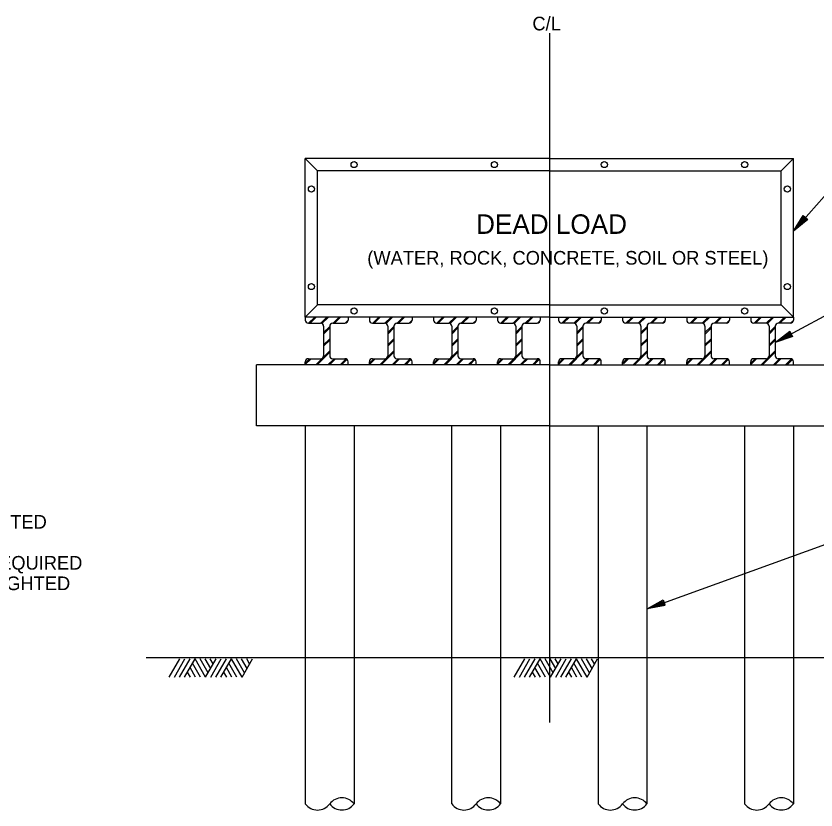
# Model space of a CAD drawing. Extents: x 22378.6 to 22422.6, y 22377.7 to 22411.7.
# Drawn here: x 22398.72 to 22406.91, y 22384.19 to 22392.32 of the extents above; entities that cross this region are included whole.
import ezdxf

# ---------------------------------------------------------------- set-up
doc = ezdxf.new("R2010")
doc.units = 0
for name, color, linetype in [('Level 1', 7, 'Continuous'), ('Level 10', 7, 'Continuous'), ('Level 2', 7, 'Continuous'), ('Level 4', 7, 'Continuous'), ('Level 7', 7, 'Continuous')]:
    doc.layers.add(name, color=color, linetype=linetype)

msp = doc.modelspace()

# ---------------------------------------------------------------- linework, layer by layer
at = {"layer": 'Level 1'}
for p, q in [((22404.1812, 22392.1476), (22404.1812, 22385.0825)), ((22406.7157, 22390.1563), (22406.7157, 22390.1563)), ((22406.6812, 22390.1173), (22406.6812, 22390.1173)), ((22401.6812, 22389.2377), (22401.6812, 22389.2064)), ((22401.7155, 22389.1753), (22401.7778, 22389.2377)), ((22401.7302, 22389.1753), (22401.7926, 22389.2377)), ((22401.8402, 22389.1751), (22401.9028, 22389.2377)), ((22401.8512, 22389.1713), (22401.9176, 22389.2377)), ((22401.9654, 22389.1752), (22402.0279, 22389.2377)), ((22401.9801, 22389.1752), (22402.0426, 22389.2377)), ((22402.1187, 22389.2377), (22402.1187, 22389.2064)), ((22402.3375, 22389.2377), (22402.3375, 22389.2064)), ((22402.3717, 22389.1752), (22402.4341, 22389.2377)), ((22402.3864, 22389.1752), (22402.4488, 22389.2377)), ((22402.4959, 22389.1744), (22402.5591, 22389.2377)), ((22402.5082, 22389.1721), (22402.5738, 22389.2377)), ((22402.6216, 22389.1751), (22402.6841, 22389.2377)), ((22402.6363, 22389.1751), (22402.6988, 22389.2377)), ((22402.775, 22389.2377), (22402.775, 22389.2064)), ((22402.9937, 22389.2377), (22402.9937, 22389.2064)), ((22403.0278, 22389.1751), (22403.0904, 22389.2377)), ((22403.0425, 22389.1751), (22403.1051, 22389.2377)), ((22403.1515, 22389.1738), (22403.2154, 22389.2377)), ((22403.1633, 22389.1709), (22403.2301, 22389.2377)), ((22403.2778, 22389.1751), (22403.3404, 22389.2377)), ((22403.2925, 22389.1751), (22403.3551, 22389.2377)), ((22403.4312, 22389.2377), (22403.4312, 22389.2064)), ((22403.65, 22389.2377), (22403.65, 22389.2064)), ((22403.684, 22389.1751), (22403.7466, 22389.2377)), ((22403.6987, 22389.1751), (22403.7613, 22389.2377)), ((22403.8093, 22389.1754), (22403.8716, 22389.2377)), ((22403.8203, 22389.1716), (22403.8863, 22389.2377)), ((22403.9342, 22389.1752), (22403.9966, 22389.2377)), ((22403.9489, 22389.1752), (22404.0113, 22389.2377)), ((22404.0875, 22389.2377), (22404.0875, 22389.2064)), ((22404.275, 22389.2377), (22404.275, 22389.2064)), ((22404.3091, 22389.1751), (22404.3717, 22389.2377)), ((22404.3238, 22389.1751), (22404.3864, 22389.2377)), ((22404.4327, 22389.1737), (22404.4967, 22389.2377)), ((22404.4448, 22389.1712), (22404.5113, 22389.2377)), ((22404.559, 22389.1751), (22404.6217, 22389.2377)), ((22404.5737, 22389.1751), (22404.6363, 22389.2377)), ((22404.7125, 22389.2377), (22404.7125, 22389.2064)), ((22404.9312, 22389.2377), (22404.9312, 22389.2064)), ((22404.9653, 22389.1751), (22405.0278, 22389.2377)), ((22404.98, 22389.1751), (22405.0425, 22389.2377)), ((22405.0905, 22389.1754), (22405.1528, 22389.2377)), ((22405.1018, 22389.1719), (22405.1675, 22389.2377)), ((22405.2154, 22389.1752), (22405.2778, 22389.2377)), ((22405.2301, 22389.1752), (22405.2925, 22389.2377)), ((22405.3687, 22389.2377), (22405.3687, 22389.2064)), ((22405.5875, 22389.2377), (22405.5875, 22389.2064)), ((22405.6217, 22389.1752), (22405.6841, 22389.2377)), ((22405.6364, 22389.1752), (22405.6988, 22389.2377)), ((22405.7462, 22389.1747), (22405.8091, 22389.2377)), ((22405.757, 22389.1708), (22405.8238, 22389.2377)), ((22405.8716, 22389.1752), (22405.9341, 22389.2377)), ((22405.8863, 22389.1752), (22405.9488, 22389.2377)), ((22406.025, 22389.2377), (22406.025, 22389.2064)), ((22406.2437, 22389.2377), (22406.2437, 22389.2064)), ((22406.2779, 22389.1752), (22406.3404, 22389.2377)), ((22406.2926, 22389.1752), (22406.3551, 22389.2377)), ((22406.4018, 22389.1741), (22406.4654, 22389.2377)), ((22406.4139, 22389.1716), (22406.4801, 22389.2377)), ((22406.5278, 22389.1751), (22406.5904, 22389.2377)), ((22406.5425, 22389.1751), (22406.6051, 22389.2377)), ((22406.6812, 22389.2377), (22406.6812, 22389.2064)), ((22401.7125, 22389.1752), (22401.8375, 22389.1752)), ((22401.8687, 22389.1439), (22401.8687, 22388.8419)), ((22401.8687, 22389.0786), (22401.9312, 22389.1411)), ((22401.9312, 22389.1439), (22401.9312, 22388.8419)), ((22401.9625, 22389.1752), (22402.0875, 22389.1752)), ((22402.0905, 22389.1753), (22402.1184, 22389.2032)), ((22402.3687, 22389.1752), (22402.4937, 22389.1752)), ((22402.525, 22389.1439), (22402.525, 22388.8419)), ((22402.525, 22389.0786), (22402.5874, 22389.1411)), ((22402.5875, 22389.1439), (22402.5875, 22388.8419)), ((22402.6187, 22389.1752), (22402.7437, 22389.1752)), ((22402.7459, 22389.1744), (22402.7734, 22389.2021)), ((22403.025, 22389.1752), (22403.15, 22389.1752)), ((22403.1812, 22389.1439), (22403.1812, 22388.8419)), ((22403.1812, 22389.0786), (22403.2437, 22389.1411)), ((22403.2437, 22389.1439), (22403.2437, 22388.8419)), ((22403.275, 22389.1752), (22403.4, 22389.1752)), ((22403.4045, 22389.1768), (22403.4316, 22389.2039)), ((22403.6812, 22389.1752), (22403.8062, 22389.1752)), ((22403.8375, 22389.1439), (22403.8375, 22388.8419)), ((22403.8375, 22389.0786), (22403.9, 22389.1411)), ((22403.9, 22389.1439), (22403.9, 22388.8419)), ((22403.9312, 22389.1752), (22404.0562, 22389.1752)), ((22404.0598, 22389.1759), (22404.0865, 22389.2026)), ((22404.4312, 22389.1752), (22404.3062, 22389.1752)), ((22404.4625, 22389.1439), (22404.4625, 22388.8419)), ((22404.4625, 22389.0786), (22404.525, 22389.1411)), ((22404.525, 22389.1439), (22404.525, 22388.8419)), ((22404.6812, 22389.1752), (22404.5562, 22389.1752)), ((22404.6857, 22389.1767), (22404.7132, 22389.2043)), ((22405.0875, 22389.1752), (22404.9625, 22389.1752)), ((22405.1187, 22389.1439), (22405.1187, 22388.8419)), ((22405.1187, 22389.0786), (22405.1812, 22389.1411)), ((22405.1812, 22389.1439), (22405.1812, 22388.8419)), ((22405.3375, 22389.1752), (22405.2125, 22389.1752)), ((22405.341, 22389.1758), (22405.3682, 22389.2031)), ((22405.7437, 22389.1752), (22405.6187, 22389.1752)), ((22405.7749, 22389.0786), (22405.8374, 22389.1411)), ((22405.775, 22389.1439), (22405.775, 22388.8419)), ((22405.8375, 22389.1439), (22405.8375, 22388.8419)), ((22405.9937, 22389.1752), (22405.8687, 22389.1752)), ((22405.9963, 22389.1749), (22406.0232, 22389.2017)), ((22406.4, 22389.1752), (22406.275, 22389.1752)), ((22406.4312, 22389.1439), (22406.4312, 22388.8419)), ((22406.4312, 22389.0786), (22406.4937, 22389.1411)), ((22406.4937, 22389.1439), (22406.4937, 22388.8419)), ((22406.65, 22389.1752), (22406.525, 22389.1752)), ((22406.6549, 22389.1773), (22406.6813, 22389.2036)), ((22401.8687, 22389.0638), (22401.9312, 22389.1263)), ((22402.525, 22389.0639), (22402.5874, 22389.1263)), ((22403.1812, 22389.0638), (22403.2437, 22389.1264)), ((22403.8375, 22389.0638), (22403.9, 22389.1263)), ((22404.4625, 22389.0638), (22404.525, 22389.1264)), ((22405.1187, 22389.0638), (22405.1812, 22389.1263)), ((22405.7739, 22389.059), (22405.8364, 22389.1215)), ((22406.4312, 22389.0639), (22406.4937, 22389.1263)), ((22401.8687, 22388.9536), (22401.9312, 22389.0161)), ((22401.8687, 22388.9388), (22401.9312, 22389.0013)), ((22402.525, 22388.9536), (22402.5874, 22389.0161)), ((22402.525, 22388.9388), (22402.5874, 22389.0013)), ((22403.1812, 22388.9536), (22403.2437, 22389.0161)), ((22403.1812, 22388.9388), (22403.2437, 22389.0013)), ((22403.8375, 22388.9536), (22403.9, 22389.0161)), ((22403.8375, 22388.9388), (22403.9, 22389.0013)), ((22404.4625, 22388.9536), (22404.525, 22389.0161)), ((22404.4625, 22388.9388), (22404.525, 22389.0013)), ((22405.1187, 22388.9536), (22405.1812, 22389.0161)), ((22405.1187, 22388.9388), (22405.1812, 22389.0013)), ((22405.7749, 22388.9536), (22405.8374, 22389.0161)), ((22405.7749, 22388.9388), (22405.8374, 22389.0013)), ((22406.4312, 22388.9536), (22406.4937, 22389.0161)), ((22406.4312, 22388.9388), (22406.4937, 22389.0013)), ((22406.4937, 22388.9771), (22406.4937, 22388.9771)), ((22406.5395, 22389.0018), (22406.5395, 22389.0018)), ((22401.6812, 22388.7661), (22401.7259, 22388.8107)), ((22401.6812, 22388.7513), (22401.7406, 22388.8107)), ((22401.7125, 22388.8107), (22401.8375, 22388.8107)), ((22401.7884, 22388.7482), (22401.9312, 22388.8911)), ((22401.8031, 22388.7482), (22401.9312, 22388.8763)), ((22401.9134, 22388.7482), (22401.9759, 22388.8107)), ((22401.9281, 22388.7482), (22401.9906, 22388.8107)), ((22401.9625, 22388.8107), (22402.0875, 22388.8107)), ((22402.3375, 22388.7661), (22402.3821, 22388.8106)), ((22402.3375, 22388.7513), (22402.3968, 22388.8106)), ((22402.3687, 22388.8107), (22402.4937, 22388.8107)), ((22402.4447, 22388.7482), (22402.5874, 22388.8911)), ((22402.4593, 22388.7482), (22402.5874, 22388.8763)), ((22402.5696, 22388.7482), (22402.6321, 22388.8107)), ((22402.5843, 22388.7482), (22402.6468, 22388.8107)), ((22402.6187, 22388.8107), (22402.7437, 22388.8107)), ((22402.9937, 22388.7661), (22403.0382, 22388.8106)), ((22402.9937, 22388.7513), (22403.053, 22388.8106)), ((22403.025, 22388.8107), (22403.15, 22388.8107)), ((22403.1009, 22388.7481), (22403.2437, 22388.8911)), ((22403.1155, 22388.7481), (22403.2437, 22388.8763)), ((22403.2259, 22388.7481), (22403.2883, 22388.8106)), ((22403.2405, 22388.7481), (22403.303, 22388.8106)), ((22403.275, 22388.8107), (22403.4, 22388.8107)), ((22403.65, 22388.7661), (22403.6947, 22388.8107)), ((22403.65, 22388.7513), (22403.7094, 22388.8107)), ((22403.6812, 22388.8107), (22403.8062, 22388.8107)), ((22403.7571, 22388.7482), (22403.9, 22388.8911)), ((22403.7718, 22388.7482), (22403.9, 22388.8763)), ((22403.8821, 22388.7482), (22403.9447, 22388.8108)), ((22403.8968, 22388.7482), (22403.9594, 22388.8108)), ((22403.9312, 22388.8107), (22404.0562, 22388.8107)), ((22404.275, 22388.7661), (22404.3195, 22388.8106)), ((22404.275, 22388.7513), (22404.3342, 22388.8106)), ((22404.4312, 22388.8107), (22404.3062, 22388.8107)), ((22404.3821, 22388.7481), (22404.525, 22388.8911)), ((22404.3968, 22388.7481), (22404.525, 22388.8763)), ((22404.5071, 22388.7481), (22404.5696, 22388.8106)), ((22404.5218, 22388.7481), (22404.5843, 22388.8106)), ((22404.6812, 22388.8107), (22404.5562, 22388.8107)), ((22404.9339, 22388.7687), (22404.9759, 22388.8107)), ((22404.9397, 22388.7597), (22404.9906, 22388.8107)), ((22405.0875, 22388.8107), (22404.9625, 22388.8107)), ((22405.0384, 22388.7482), (22405.1812, 22388.8911)), ((22405.0531, 22388.7482), (22405.1812, 22388.8763)), ((22405.1634, 22388.7482), (22405.2258, 22388.8106)), ((22405.178, 22388.7482), (22405.2404, 22388.8106)), ((22405.3375, 22388.8107), (22405.2125, 22388.8107)), ((22405.5875, 22388.7661), (22405.6321, 22388.8107)), ((22405.5875, 22388.7513), (22405.6468, 22388.8107)), ((22405.7437, 22388.8107), (22405.6187, 22388.8107)), ((22405.6946, 22388.7482), (22405.8374, 22388.8911)), ((22405.7093, 22388.7482), (22405.8374, 22388.8763)), ((22405.8196, 22388.7482), (22405.8822, 22388.8107)), ((22405.8343, 22388.7482), (22405.8969, 22388.8107)), ((22405.9937, 22388.8107), (22405.8687, 22388.8107)), ((22406.2437, 22388.7661), (22406.2883, 22388.8106)), ((22406.2437, 22388.7513), (22406.303, 22388.8106)), ((22406.4, 22388.8107), (22406.275, 22388.8107)), ((22406.3509, 22388.7482), (22406.4937, 22388.8911)), ((22406.3656, 22388.7482), (22406.4937, 22388.8762)), ((22406.4759, 22388.7482), (22406.5383, 22388.8107)), ((22406.4906, 22388.7482), (22406.5531, 22388.8107)), ((22406.65, 22388.8107), (22406.525, 22388.8107)), ((22401.6812, 22388.7482), (22401.6812, 22388.7794)), ((22402.0384, 22388.7482), (22402.0992, 22388.8091)), ((22402.0531, 22388.7482), (22402.1072, 22388.8023)), ((22402.1187, 22388.7482), (22402.1187, 22388.7794)), ((22402.3375, 22388.7482), (22402.3375, 22388.7794)), ((22402.6947, 22388.7482), (22402.7548, 22388.8083)), ((22402.7094, 22388.7482), (22402.7632, 22388.8021)), ((22402.775, 22388.7482), (22402.775, 22388.7794)), ((22402.9937, 22388.7482), (22402.9937, 22388.7794)), ((22403.3509, 22388.7481), (22403.4103, 22388.8076)), ((22403.3656, 22388.7481), (22403.4193, 22388.8019)), ((22403.4312, 22388.7482), (22403.4312, 22388.7794)), ((22403.65, 22388.7482), (22403.65, 22388.7794)), ((22404.0071, 22388.7482), (22404.0679, 22388.8089)), ((22404.0218, 22388.7482), (22404.0771, 22388.8036)), ((22404.0875, 22388.7482), (22404.0875, 22388.7794)), ((22404.275, 22388.7482), (22404.275, 22388.7794)), ((22404.6321, 22388.7481), (22404.6927, 22388.8087)), ((22404.6468, 22388.7481), (22404.701, 22388.8023)), ((22404.7125, 22388.7482), (22404.7125, 22388.7794)), ((22404.9312, 22388.7482), (22404.9312, 22388.7794)), ((22405.2884, 22388.7482), (22405.3482, 22388.8081)), ((22405.303, 22388.7482), (22405.357, 22388.8021)), ((22405.3687, 22388.7482), (22405.3687, 22388.7794)), ((22405.5875, 22388.7482), (22405.5875, 22388.7794)), ((22405.9446, 22388.7482), (22406.0058, 22388.8093)), ((22405.9593, 22388.7482), (22406.0131, 22388.8019)), ((22406.025, 22388.7482), (22406.025, 22388.7794)), ((22406.2437, 22388.7482), (22406.2437, 22388.7794)), ((22406.6009, 22388.7482), (22406.6613, 22388.8086)), ((22406.6156, 22388.7482), (22406.6709, 22388.8036)), ((22406.6812, 22388.7482), (22406.6812, 22388.7794)), ((22405.1812, 22386.2472), (22405.1812, 22386.2472)), ((22405.2301, 22386.2649), (22405.2301, 22386.2649)), ((22400.2882, 22385.5474), (22400.3964, 22385.7349)), ((22400.3402, 22385.5474), (22400.4484, 22385.7349)), ((22400.3922, 22385.5474), (22400.5004, 22385.7349)), ((22400.4441, 22385.5474), (22400.5523, 22385.7349)), ((22400.6606, 22385.5474), (22400.5523, 22385.7349)), ((22400.6866, 22385.5924), (22400.6043, 22385.7349)), ((22400.7126, 22385.6374), (22400.6563, 22385.7349)), ((22400.6606, 22385.5474), (22400.7688, 22385.7348)), ((22400.7386, 22385.6824), (22400.7083, 22385.7349)), ((22400.7126, 22385.5474), (22400.8209, 22385.7349)), ((22400.7644, 22385.5474), (22400.8728, 22385.7349)), ((22400.8164, 22385.5474), (22400.9248, 22385.7349)), ((22401.0331, 22385.5474), (22400.9248, 22385.7349)), ((22401.0591, 22385.5924), (22400.9768, 22385.7349)), ((22401.0851, 22385.6374), (22401.0288, 22385.7349)), ((22401.0331, 22385.5474), (22401.1414, 22385.7349)), ((22401.1111, 22385.6824), (22401.0808, 22385.7349)), ((22403.8216, 22385.5474), (22403.9299, 22385.7349)), ((22403.8736, 22385.5474), (22403.9819, 22385.7349)), ((22403.9256, 22385.5474), (22404.0339, 22385.7349)), ((22403.9775, 22385.5474), (22404.0857, 22385.7349)), ((22404.194, 22385.5474), (22404.0857, 22385.7349)), ((22404.22, 22385.5924), (22404.1377, 22385.7349)), ((22404.246, 22385.6374), (22404.1897, 22385.7349)), ((22404.194, 22385.5474), (22404.3022, 22385.7348)), ((22404.272, 22385.6824), (22404.2417, 22385.7349)), ((22404.246, 22385.5474), (22404.3544, 22385.7349)), ((22404.2979, 22385.5474), (22404.4062, 22385.7349)), ((22404.3499, 22385.5474), (22404.4582, 22385.7349)), ((22404.5665, 22385.5474), (22404.4582, 22385.7349)), ((22404.5925, 22385.5924), (22404.5102, 22385.7349)), ((22404.6185, 22385.6374), (22404.5622, 22385.7349)), ((22404.5665, 22385.5474), (22404.6749, 22385.7349)), ((22404.6445, 22385.6824), (22404.6142, 22385.7349)), ((22400.5566, 22385.5474), (22400.5003, 22385.6449)), ((22400.6086, 22385.5474), (22400.5263, 22385.6899)), ((22400.9291, 22385.5474), (22400.8728, 22385.6449)), ((22400.9811, 22385.5474), (22400.8988, 22385.6899)), ((22404.09, 22385.5474), (22404.0337, 22385.6449)), ((22404.142, 22385.5474), (22404.0597, 22385.6899)), ((22404.4625, 22385.5474), (22404.4062, 22385.6449)), ((22404.5145, 22385.5474), (22404.4322, 22385.6899)), ((22400.5047, 22385.5474), (22400.4744, 22385.5999)), ((22400.8772, 22385.5474), (22400.8469, 22385.5999)), ((22404.0381, 22385.5474), (22404.0079, 22385.5999)), ((22404.4106, 22385.5474), (22404.3804, 22385.5999))]:
    msp.add_line(p, q, dxfattribs=at)
for points in [[(22406.6812, 22390.1173), (22407.3105, 22390.8281), (22407.6069, 22390.8281)], [(22406.8284, 22390.2368), (22406.6812, 22390.1173), (22406.782, 22390.2779), (22406.8217, 22390.2428), (22406.7157, 22390.1563), (22406.7842, 22390.2653), (22406.8096, 22390.2427), (22406.7489, 22390.1937), (22406.7864, 22390.2527), (22406.7968, 22390.2434), (22406.7833, 22390.2326)], [(22406.4937, 22388.9771), (22407.2684, 22389.3939), (22407.5648, 22389.3939)], [(22406.6731, 22389.0384), (22406.4937, 22388.9771), (22406.6437, 22389.093), (22406.6688, 22389.0464), (22406.5395, 22389.0018), (22406.6414, 22389.0804), (22406.6575, 22389.0505), (22406.5836, 22389.0255), (22406.6391, 22389.0679), (22406.6457, 22389.0555), (22406.6294, 22389.0501)], [(22405.1812, 22386.2472), (22407.7285, 22387.1692), (22408.0249, 22387.1692)], [(22405.3676, 22386.2817), (22405.1812, 22386.2472), (22405.3465, 22386.34), (22405.3646, 22386.2902), (22405.2301, 22386.2649), (22405.3424, 22386.3279), (22405.354, 22386.2959), (22405.2771, 22386.2819), (22405.3383, 22386.3158), (22405.3431, 22386.3026), (22405.326, 22386.2996)]]:
    msp.add_lwpolyline(points, dxfattribs=at)
for centre in [(22402.1812, 22390.8002), (22403.6187, 22390.8002), (22404.7437, 22390.8002), (22406.1812, 22390.8002), (22401.7437, 22390.5502), (22406.6187, 22390.5502), (22401.7437, 22389.5502), (22406.6187, 22389.5502), (22402.1812, 22389.3002), (22403.6187, 22389.3002), (22404.7437, 22389.3002), (22406.1812, 22389.3002)]:
    msp.add_circle(centre, 0.0313, dxfattribs=at)
for centre, radius, start, end in [((22401.7124, 22389.2064), 0.0311, 179.85557, 270.33541), ((22401.8374, 22389.1439), 0.0314, 0.12099, 89.68802), ((22401.9625, 22389.144), 0.0313, 89.99062, 180.00938), ((22402.0875, 22389.2064), 0.0312, 269.98594, 0.01406), ((22402.3687, 22389.2064), 0.0312, 179.98594, 270.01406), ((22402.4937, 22389.144), 0.0313, 359.99062, 90.00938), ((22402.6187, 22389.1441), 0.0311, 89.85557, 180.33541), ((22402.7437, 22389.2066), 0.0314, 270.12099, 359.68802), ((22403.0249, 22389.2064), 0.0311, 179.85557, 270.33541), ((22403.1499, 22389.1439), 0.0314, 0.12099, 89.68802), ((22403.275, 22389.144), 0.0313, 89.99062, 180.00938), ((22403.4, 22389.2064), 0.0312, 269.98594, 0.01406), ((22403.6812, 22389.2064), 0.0312, 179.98594, 270.01406), ((22403.8062, 22389.144), 0.0313, 359.99062, 90.00938), ((22403.9312, 22389.1441), 0.0311, 89.85557, 180.33541), ((22404.0562, 22389.2066), 0.0314, 270.12099, 359.68802), ((22404.3062, 22389.2064), 0.0312, 179.98594, 270.01405), ((22404.4312, 22389.144), 0.0313, 359.99061, 90.00938), ((22404.5564, 22389.1439), 0.0314, 90.31198, 179.87901), ((22404.6814, 22389.2064), 0.0311, 269.66458, 0.14443), ((22404.9626, 22389.2066), 0.0314, 180.31197, 269.879), ((22405.0876, 22389.1441), 0.0311, 359.66458, 90.14443), ((22405.2125, 22389.144), 0.0313, 89.99061, 180.00938), ((22405.3375, 22389.2064), 0.0312, 269.98594, 0.01405), ((22405.6187, 22389.2064), 0.0312, 179.98594, 270.01405), ((22405.7437, 22389.144), 0.0313, 359.99061, 90.00938), ((22405.8689, 22389.1439), 0.0314, 90.31198, 179.87901), ((22405.9939, 22389.2064), 0.0311, 269.66458, 0.14443), ((22406.2751, 22389.2066), 0.0314, 180.31197, 269.879), ((22406.4001, 22389.1441), 0.0311, 359.66458, 90.14443), ((22406.525, 22389.144), 0.0313, 89.99061, 180.00938), ((22406.65, 22389.2064), 0.0312, 269.98594, 0.01405), ((22401.7125, 22388.7795), 0.0313, 89.99062, 180.00938), ((22401.8375, 22388.8419), 0.0312, 269.98594, 0.01406), ((22401.9624, 22388.8419), 0.0311, 179.85557, 270.33541), ((22402.0874, 22388.7794), 0.0314, 0.12099, 89.68802), ((22402.3687, 22388.7796), 0.0311, 89.85557, 180.33541), ((22402.4937, 22388.8421), 0.0314, 270.12099, 359.68802), ((22402.6187, 22388.8419), 0.0312, 179.98594, 270.01406), ((22402.7437, 22388.7795), 0.0313, 359.99062, 90.00938), ((22403.025, 22388.7795), 0.0313, 89.99062, 180.00938), ((22403.15, 22388.8419), 0.0312, 269.98594, 0.01406), ((22403.2749, 22388.8419), 0.0311, 179.85557, 270.33541), ((22403.3999, 22388.7794), 0.0314, 0.12099, 89.68802), ((22403.6812, 22388.7796), 0.0311, 89.85557, 180.33541), ((22403.8062, 22388.8421), 0.0314, 270.12099, 359.68802), ((22403.9312, 22388.8419), 0.0312, 179.98594, 270.01406), ((22404.0562, 22388.7795), 0.0313, 359.99062, 90.00938), ((22404.3064, 22388.7794), 0.0314, 90.31198, 179.87901), ((22404.4314, 22388.8419), 0.0311, 269.66458, 0.14443), ((22404.5562, 22388.8419), 0.0312, 179.98594, 270.01405), ((22404.6812, 22388.7795), 0.0313, 359.99061, 90.00938), ((22404.9625, 22388.7795), 0.0313, 89.99061, 180.00938), ((22405.0875, 22388.8419), 0.0312, 269.98594, 0.01405), ((22405.2126, 22388.8421), 0.0314, 180.31197, 269.879), ((22405.3376, 22388.7796), 0.0311, 359.66458, 90.14443), ((22405.6189, 22388.7794), 0.0314, 90.31198, 179.87901), ((22405.7439, 22388.8419), 0.0311, 269.66458, 0.14443), ((22405.8687, 22388.8419), 0.0312, 179.98594, 270.01405), ((22405.9937, 22388.7795), 0.0313, 359.99061, 90.00938), ((22406.275, 22388.7795), 0.0313, 89.99061, 180.00938), ((22406.4, 22388.8419), 0.0312, 269.98594, 0.01405), ((22406.5251, 22388.8421), 0.0314, 180.31198, 269.87901), ((22406.6501, 22388.7796), 0.0311, 359.66458, 90.14443)]:
    msp.add_arc(centre, radius, start, end, dxfattribs=at)
at = {"layer": 'Level 2'}
for p, q in [((22404.1812, 22390.8627), (22401.6812, 22390.8627)), ((22401.6812, 22389.2377), (22401.6812, 22390.8627)), ((22401.6812, 22390.8627), (22401.8062, 22390.7377)), ((22404.1812, 22390.8627), (22406.6812, 22390.8627)), ((22406.6812, 22390.8627), (22406.5562, 22390.7377)), ((22406.6812, 22389.2377), (22406.6812, 22390.8627)), ((22401.8062, 22389.3627), (22401.8062, 22390.7377)), ((22404.1812, 22390.7377), (22401.8062, 22390.7377)), ((22404.1812, 22390.7377), (22406.5562, 22390.7377)), ((22406.5562, 22389.3627), (22406.5562, 22390.7377)), ((22401.6812, 22389.2377), (22401.8062, 22389.3627)), ((22404.1812, 22389.3627), (22401.8062, 22389.3627)), ((22404.1812, 22389.3627), (22406.5562, 22389.3627)), ((22406.6812, 22389.2377), (22406.5562, 22389.3627)), ((22404.1812, 22389.2377), (22401.6812, 22389.2377)), ((22404.1812, 22389.2377), (22406.6812, 22389.2377)), ((22400.0525, 22385.7482), (22408.1772, 22385.7482)), ((22401.6812, 22385.7482), (22401.6812, 22384.2482)), ((22402.1812, 22385.7482), (22402.1812, 22384.2482)), ((22403.1812, 22384.2482), (22403.1812, 22385.7482)), ((22403.6812, 22385.7482), (22403.6812, 22384.2482)), ((22404.6812, 22385.7482), (22404.6812, 22384.2482)), ((22405.1812, 22384.2482), (22405.1812, 22385.7482)), ((22406.1812, 22385.7482), (22406.1812, 22384.2482)), ((22406.6812, 22385.7482), (22406.6812, 22384.2482))]:
    msp.add_line(p, q, dxfattribs=at)
for centre, radius, start, end in [((22402.0559, 22384.1547), 0.156, 36.84504, 143.15496), ((22403.5559, 22384.1547), 0.156, 36.84504, 143.15496), ((22405.0559, 22384.1547), 0.156, 36.84504, 143.15496), ((22406.5559, 22384.1547), 0.156, 36.84504, 143.15496), ((22401.8061, 22384.3419), 0.1561, 216.86416, 323.13584), ((22402.0559, 22384.342), 0.1561, 216.90623, 323.09376), ((22403.3061, 22384.3419), 0.1561, 216.86416, 323.13584), ((22403.5559, 22384.342), 0.1561, 216.90623, 323.09376), ((22404.8061, 22384.3419), 0.1561, 216.86416, 323.13584), ((22405.0559, 22384.342), 0.1561, 216.90623, 323.09376), ((22406.3061, 22384.3419), 0.1561, 216.86416, 323.13584), ((22406.5559, 22384.342), 0.1561, 216.90623, 323.09376)]:
    msp.add_arc(centre, radius, start, end, dxfattribs=at)
at = {"layer": 'Level 7'}
for p, q in [((22404.1812, 22388.7482), (22401.1812, 22388.7482)), ((22401.1812, 22388.1232), (22401.1812, 22388.7482)), ((22404.1812, 22388.7482), (22407.1812, 22388.7482)), ((22404.1812, 22388.1232), (22401.1812, 22388.1232)), ((22401.6812, 22388.1232), (22401.6812, 22385.7482)), ((22402.1812, 22388.1232), (22402.1812, 22385.7482)), ((22403.1812, 22385.7482), (22403.1812, 22388.1232)), ((22403.6812, 22388.1232), (22403.6812, 22385.7482)), ((22404.1812, 22388.1232), (22407.1812, 22388.1232)), ((22404.6812, 22388.1232), (22404.6812, 22385.7482)), ((22405.1812, 22385.7482), (22405.1812, 22388.1232)), ((22406.1812, 22388.1232), (22406.1812, 22385.7482)), ((22406.6812, 22388.1232), (22406.6812, 22385.7482))]:
    msp.add_line(p, q, dxfattribs=at)

# ---------------------------------------------------------------- texts
at = {"layer": 'Level 10'}
msp.add_text('DEAD LOAD', height=0.2, dxfattribs=at).set_placement((22403.4302, 22390.0903))
at = {"layer": 'Level 4'}
for s, p in [('C/L', (22404.0075, 22392.1756)), ('(WATER, ROCK, CONCRETE, SOIL OR STEEL)', (22402.3161, 22389.7748)), ('CONTRACTOR CAN USE WEIGHTED', (22395.7676, 22387.069)), ('HAND THAT WILL RESULT IN REQUIRED', (22395.7676, 22386.649)), ('DEAD LOAD. (EXAMPLE OF WEIGHTED', (22395.7676, 22386.439))]:
    msp.add_text(s, height=0.14, dxfattribs=at).set_placement(p)

doc.saveas('drawing.dxf')
